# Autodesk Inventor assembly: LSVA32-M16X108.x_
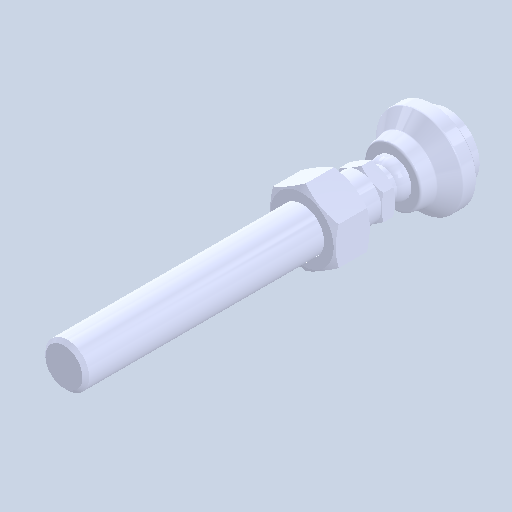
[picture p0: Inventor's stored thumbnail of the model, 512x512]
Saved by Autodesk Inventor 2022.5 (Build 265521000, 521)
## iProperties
Created: 2024-08
Part Number: LSVA32-M16X108.x_
Document SubType Name: Assembly
Designer: ImaoCorp
Author: ImaoCorp
Sending System: SOLIDWORKS 2022-2022290
MC: AMD64
MC_MODEL: Intel64 Family 6 Model 60 Stepping 3, GenuineIntel
OS: Windows_NT
FRU: Parasolid Version 33.1, build 260,  4-25-2022
FORMAT: text
GUISE: transmit
KEY: FILELSVA32-M16X108.x_t
DATE: Fri Aug 23 16:06:45 2024
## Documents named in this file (4)
- X:\14_SW2022-Inv2022\06_2024-10新製品(SME)\ELS_データ\l\lsva32-m16x108\LSVA32-M16X108.x_.iam
- X:\14_SW2022-Inv2022\06_2024-10新製品(SME)\ELS_データ\l\lsva32-m16x108\LSVA32-M16X108_01.ipt
- X:\14_SW2022-Inv2022\06_2024-10新製品(SME)\ELS_データ\l\lsva32-m16x108\LSVA32-M16X108_02.ipt
- X:\14_SW2022-Inv2022\06_2024-10新製品(SME)\ELS_データ\l\lsva32-m16x108\LSVA32-M16X108_03.ipt
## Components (3 placed, 3 different names)
1. LSVA32-M16X108_01
2. LSVA32-M16X108_02
3. LSVA32-M16X108_03
